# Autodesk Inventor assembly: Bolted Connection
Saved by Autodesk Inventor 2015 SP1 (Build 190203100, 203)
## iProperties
Created: 2011-06
Part Number: Bolted Connection
Document SubType Name: Assembly
Designer: Guilherme Augusto Franco de Souza
ClientObjectVersion: 1
Author: Guilherme Augusto Franco de Souza
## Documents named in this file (4)
- E:\Visitor Experience Project\WSI2015 - Visitor Experience Project\#46- Sheet Metal Technology\01- 3D Models\Outodoor Heater\2- Assemblies\Outdoor Heater\Design Accelerator\Bolted Connection2.iam
- C:\Users\Guilherme Augusto\Documents\Inventor\Content Center Files\R2015\en-US\ISO 7089\ISO 7089 - 6 - 140 HV(1).ipt
- C:\Users\Guilherme Augusto\Documents\Inventor\Content Center Files\R2015\en-US\ISO 4017(1)\ISO 4017 - M6 x 40ISO.ipt
- C:\Users\Guilherme Augusto\Documents\Inventor\Content Center Files\R2015\en-US\ISO 4032(2)\ISO 4032 - M6ISO.ipt
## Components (16 placed, 3 different names)
1. ISO 7089 6 - 140 HV:9
2. ISO 4017 M6 x 40:5
3. ISO 7089 6 - 140 HV:10
4. ISO 4032 M6:5
5. ISO 4017 M6 x 40:2
6. ISO 4017 M6 x 40:3
7. ISO 4017 M6 x 40:4
8. ISO 7089 6 - 140 HV:3
9. ISO 7089 6 - 140 HV:4
10. ISO 7089 6 - 140 HV:5
11. ISO 7089 6 - 140 HV:6
12. ISO 7089 6 - 140 HV:7
13. ISO 7089 6 - 140 HV:8
14. ISO 4032 M6:2
15. ISO 4032 M6:3
16. ISO 4032 M6:4
